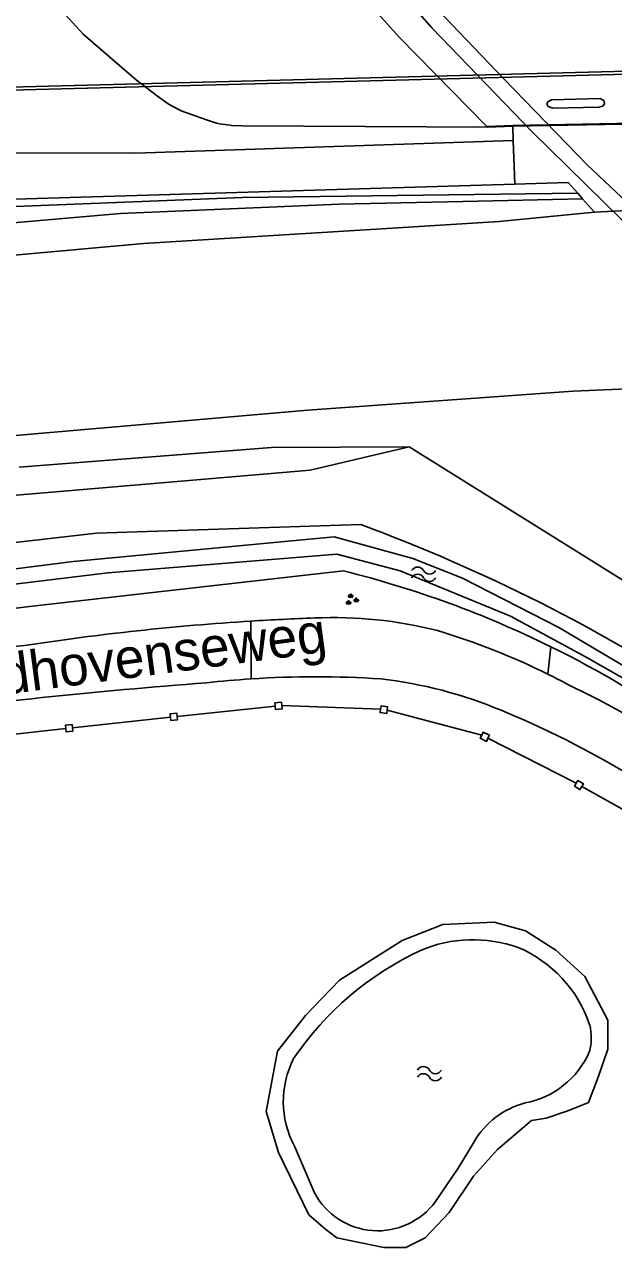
# Model space of a CAD drawing. Extents: x 135990 to 139000, y 393500 to 396000.
# Drawn here: x 137162.5 to 137199.5, y 395776.9 to 395853.7 of the extents above; entities that cross this region are included whole.
import ezdxf

# ---------------------------------------------------------------- set-up
doc = ezdxf.new("R2010")
doc.units = 0
for name, color, linetype in [('gg-afsc-hekwerk', 7, 'Continuous'), ('gg-afsc-muur', 7, 'Continuous'), ('gg-anno-openbare ruimte label', 7, 'Continuous'), ('gg-knt-BGT kruinlijn', 7, 'Continuous'), ('gg-knt-verharding', 7, 'Continuous'), ('gg-kntw-bovenkant insteek waterloop', 7, 'Continuous'), ('gg-kntw-waterlijn', 7, 'Continuous'), ('gg-kwrk-faunavoorziening', 7, 'Continuous'), ('gg-kwrk-kunstwerk niveau 01', 7, 'Continuous'), ('gt-grn-groengrens', 7, 'Continuous'), ('gt-grn-weggrens', 7, 'Continuous'), ('gt-symb-groenvak', 7, 'Continuous'), ('gt-symb-watersymbool', 7, 'Continuous'), ('gx-grn-maaiveld', 7, 'Continuous')]:
    doc.layers.add(name, color=color, linetype=linetype)

# ---------------------------------------------------------------- blocks, each defined once
blk = doc.blocks.new('gt0-GRVAK')
at = {"layer": 'gt-symb-groenvak'}
for p, q in [((-0.11, 0.189), (-0.228, 0.24)), ((-0.182, 0.153), (0.088, 0.153)), ((-0.091, 0.211), (-0.156, 0.322)), ((-0.047, 0.214), (-0.047, 0.393)), ((-0.004, 0.211), (0.061, 0.322)), ((0.015, 0.189), (0.133, 0.24)), ((0.262, -0.052), (0.197, 0.059)), ((0.305, -0.049), (0.305, 0.13)), ((0.349, -0.052), (0.414, 0.059)), ((-0.245, -0.228), (-0.363, -0.177)), ((-0.318, -0.264), (-0.047, -0.264)), ((-0.226, -0.206), (-0.291, -0.095)), ((-0.183, -0.203), (-0.183, -0.024)), ((-0.139, -0.206), (-0.074, -0.095)), ((-0.12, -0.228), (-0.002, -0.177)), ((0.243, -0.074), (0.125, -0.023)), ((0.17, -0.11), (0.441, -0.11)), ((0.368, -0.074), (0.486, -0.023))]:
    blk.add_line(p, q, dxfattribs=at)
blk = doc.blocks.new('gt0-WA')
at = {"layer": 'gt-symb-watersymbool'}
for centre, start, end in [((-0.323, 0.022), 28.07249, 151.92751), ((0.427, 0.422), 208.07248, 331.92751), ((-0.323, -0.428), 28.07249, 151.92751), ((0.427, -0.028), 208.07248, 331.92751)]:
    blk.add_arc(centre, 0.425, start, end, dxfattribs=at)

msp = doc.modelspace()

# ---------------------------------------------------------------- linework, layer by layer
at = {"layer": 'gg-afsc-hekwerk'}
for p, q in [((137178.271, 395810.926), (137172.107, 395810.279)), ((137178.271, 395810.926), (137172.107, 395810.279)), ((137178.689, 395810.968), (137184.876, 395810.739)), ((137178.689, 395810.968), (137184.876, 395810.739)), ((137185.29, 395810.681), (137186.617, 395810.327)), ((137185.29, 395810.681), (137186.617, 395810.327)), ((137171.689, 395810.241), (137165.544, 395809.566)), ((137171.689, 395810.241), (137165.544, 395809.566)), ((137186.617, 395810.327), (137191.218, 395809.1)), ((137186.617, 395810.327), (137191.218, 395809.1)), ((137165.125, 395809.535), (137158.966, 395808.841)), ((137165.125, 395809.535), (137158.966, 395808.841)), ((137191.615, 395808.91), (137197.144, 395806.089)), ((137191.615, 395808.91), (137197.144, 395806.089)), ((137197.495, 395805.877), (137202.906, 395802.862)), ((137197.495, 395805.877), (137202.906, 395802.862))]:
    msp.add_line(p, q, dxfattribs=at)
at = {"layer": 'gg-afsc-muur'}
for points in [[(137178.689, 395810.968), (137178.669, 395811.175), (137178.251, 395811.134), (137178.271, 395810.926)], [(137178.689, 395810.968), (137178.71, 395810.76), (137178.292, 395810.719), (137178.271, 395810.926)], [(137185.29, 395810.681), (137185.261, 395810.473), (137184.847, 395810.531), (137184.876, 395810.739)], [(137185.29, 395810.681), (137185.319, 395810.889), (137184.905, 395810.947), (137184.876, 395810.739)], [(137165.544, 395809.566), (137165.529, 395809.776), (137165.11, 395809.745), (137165.125, 395809.535)], [(137172.107, 395810.279), (137172.088, 395810.491), (137171.67, 395810.453), (137171.689, 395810.241)], [(137172.107, 395810.279), (137172.127, 395810.068), (137171.709, 395810.029), (137171.689, 395810.241)], [(137165.544, 395809.566), (137165.559, 395809.356), (137165.141, 395809.325), (137165.125, 395809.535)], [(137191.615, 395808.91), (137191.524, 395808.72), (137191.127, 395808.911), (137191.218, 395809.1)], [(137191.615, 395808.91), (137191.706, 395809.099), (137191.309, 395809.289), (137191.218, 395809.1)], [(137197.495, 395805.877), (137197.386, 395805.697), (137197.035, 395805.909), (137197.144, 395806.089)], [(137197.495, 395805.877), (137197.603, 395806.056), (137197.252, 395806.268), (137197.144, 395806.089)]]:
    msp.add_lwpolyline(points, dxfattribs=at)
at = {"layer": 'gg-knt-BGT kruinlijn'}
for p, q in [((137178.024, 395827.169), (137162.207, 395825.928)), ((137186.663, 395827.215), (137178.024, 395827.169))]:
    msp.add_line(p, q, dxfattribs=at)
msp.add_lwpolyline([(137092.226, 395833.606), (137099.988, 395834.818), (137105.894, 395835.651), (137111.463, 395836.46), (137116.876, 395837.408), (137122.429, 395838.307), (137129.831, 395839.156), (137136.568, 395839.864), (137142.557, 395840.521), (137146.722, 395840.897), (137149.415, 395840.991), (137151.889, 395840.889), (137157.241, 395840.874), (137163.262, 395841.406), (137168.559, 395841.856), (137175.926, 395842.169), (137182.267, 395842.447), (137190.034, 395842.604), (137197.551, 395842.78)], dxfattribs=at)
at = {"layer": 'gg-knt-verharding'}
msp.add_line((137192.786, 395810.523), (137192.444, 395810.669), dxfattribs=at)
for centre, radius, start, end in [((137186.403, 395660.502), 156.065, 93.54873, 98.79787), ((137186.55, 395657.859), 158.713, 92.09664, 93.54244), ((137181.905, 395789.863), 26.627, 75.76685, 92.50151), ((137175.427, 395772.596), 45.003, 63.68661, 73.17643), ((137196.095, 395406.981), 409.129, 94.70544, 99.73883), ((137174.749, 395771.265), 46.497, 61.99483, 63.6653), ((137201.614, 395448.868), 364.58, 94.35164, 97.60878), ((137180.792, 395750.403), 62.37, 93.71847, 96.29705), ((137180.808, 395750.713), 62.062, 86.23421, 93.7517), ((137181.77, 395785.227), 27.59, 67.24052, 83.5202), ((137162.487, 395742.046), 78.105, 57.45807, 64.11745), ((137169.53, 395755.208), 60.005, 64.88767, 67.19698), ((137169.235, 395754.525), 60.749, 56.21195, 64.90924)]:
    msp.add_arc(centre, radius, start, end, dxfattribs=at)
at = {"layer": 'gg-kntw-bovenkant insteek waterloop'}
for p, q in [((137167.056, 395821.795), (137183.632, 395822.326)), ((137162.838, 395817.179), (137182.557, 395819.42)), ((137180.725, 395780.382), (137179.469, 395783.311))]:
    msp.add_line(p, q, dxfattribs=at)
for points in [[(137000, 395789.345), (137007.08, 395791.511), (137047.79, 395801.851), (137091.42, 395811.382), (137130.73, 395817.622), (137167.056, 395821.795)], [(137162.838, 395817.179), (137131.48, 395813.262), (137090.45, 395806.152), (137047.99, 395796.692), (137042.383, 395795.217)], [(137180.383, 395778.992), (137178.462, 395782.915), (137177.692, 395785.49), (137178.409, 395789.266), (137180.156, 395791.518), (137182.292, 395793.722), (137186.226, 395796.225), (137188.774, 395797.223), (137191.993, 395797.364)], [(137180.383, 395778.992), (137181.446, 395778.081), (137182.129, 395777.549), (137185.088, 395776.942), (137186.454, 395776.942), (137187.668, 395777.549), (137189.185, 395779.144), (137190.703, 395781.421), (137192.221, 395783.091), (137194.345, 395784.913), (137195.256, 395785.065), (137196.622, 395785.521), (137197.912, 395786.052), (137198.519, 395787.646), (137199.126, 395789.393), (137199.126, 395791.215), (137197.684, 395793.948), (137195.863, 395795.618), (137193.966, 395796.832), (137191.993, 395797.364)], [(137188.322, 395779.831), (137189.748, 395781.932), (137190.742, 395783.578)]]:
    msp.add_lwpolyline(points, dxfattribs=at)
for centre, radius, start, end in [((137146.605, 395721.892), 107.042, 56.61581, 69.76268), ((137166.969, 395756.698), 64.63, 63.74429, 76.04345), ((137167.018, 395756.748), 64.563, 54.71856, 63.76314)]:
    msp.add_arc(centre, radius, start, end, dxfattribs=at)
at = {"layer": 'gg-kntw-waterlijn'}
for points in [[(136968.737, 395777.398), (136994.091, 395785.32), (137025.448, 395794.333), (137033.646, 395796.495), (137060.818, 395803.1), (137072.955, 395805.786), (137085.527, 395808.569), (137095.686, 395810.408), (137116.952, 395814.005), (137134.131, 395816.331), (137142.583, 395817.284), (137155.856, 395818.782), (137165.595, 395820.017), (137181.967, 395821.568), (137186.891, 395820.194), (137190.02, 395818.97), (137196.065, 395815.871), (137202.42, 395812.104)], [(137229.766, 395795.804), (137197.765, 395813.996), (137193.031, 395816.57), (137186.114, 395819.434), (137182.135, 395820.479), (137167.756, 395819.294), (137153.141, 395817.514), (137121.302, 395813.334), (137111.341, 395811.713), (137088.362, 395807.588), (137062.841, 395802.174), (137044.636, 395798.052), (137025.44, 395793.193), (137014.589, 395790.094), (136993.792, 395783.757), (136971.502, 395777.034)]]:
    msp.add_lwpolyline(points, dxfattribs=at)
for centre, radius, start, end in [((137190.683, 395787.81), 8.455, 70.5015, 112.99597), ((137195.809, 395777.638), 19.835, 115.14718, 145.72628), ((137190.394, 395788.399), 8.009, 18.42638, 67.14533), ((137194.865, 395790.117), 3.233, 344.06263, 14.59088), ((137192.922, 395791.437), 5.512, 280.74829, 336.39047), ((137184.742, 395786.109), 5.969, 153.11298, 207.95015), ((137195.294, 395780.929), 5.266, 104.78058, 149.80041), ((137184.696, 395782.487), 4.494, 207.92523, 323.77813)]:
    msp.add_arc(centre, radius, start, end, dxfattribs=at)
at = {"layer": 'gg-kwrk-faunavoorziening'}
msp.add_lwpolyline([(137160.001, 395849.554), (137159.996, 395849.754), (137235.826, 395851.724), (137235.831, 395851.524), (137160.001, 395849.554)], dxfattribs=at)
at = {"layer": 'gg-kwrk-kunstwerk niveau 01'}
for points in [[(137226.693, 395820.807), (137224.986, 395820.706), (137219.386, 395824.923), (137213.014, 395829.943), (137206.497, 395835.519), (137199.981, 395841.471), (137194.38, 395846.985), (137188.095, 395853.509), (137186.573, 395855.275), (137187.949, 395855.178)], [(137226.693, 395820.807), (137219.124, 395826.392), (137212.027, 395832.143), (137205.256, 395837.932), (137197.858, 395844.884), (137192.612, 395850.303), (137187.949, 395855.178)]]:
    msp.add_lwpolyline(points, dxfattribs=at)
at = {"layer": 'gt-grn-groengrens'}
msp.add_line((137195.56, 395814.66), (137195.376, 395812.936), dxfattribs=at)
at = {"layer": 'gt-grn-weggrens'}
msp.add_line((137176.743, 395816.268), (137176.747, 395812.642), dxfattribs=at)
at = {"layer": 'gx-grn-maaiveld'}
for p, q in [((137193.165, 395847.335), (137213.85, 395847.728)), ((137191.548, 395847.33), (137191.595, 395847.282)), ((137191.595, 395847.282), (137193.165, 395847.335)), ((137193.199, 395846.445), (137193.165, 395847.335)), ((137193.303, 395843.697), (137193.199, 395846.445)), ((137197.551, 395842.78), (137197.241, 395843.128)), ((137197.551, 395842.78), (137198.302, 395841.933)), ((137198.302, 395841.933), (137198.691, 395841.954)), ((137186.663, 395827.215), (137180.449, 395825.747)), ((137201.277, 395818.076), (137186.663, 395827.215)), ((137180.449, 395825.747), (137170.399, 395824.883)), ((137170.399, 395824.883), (137156.193, 395823.678))]:
    msp.add_line(p, q, dxfattribs=at)
for points in [[(137130.328, 395893.164), (137140.225, 395881.266), (137157.02, 395863.192), (137166.224, 395853.125), (137169.557, 395850.228), (137170.872, 395849.221), (137171.545, 395848.742), (137171.653, 395848.676), (137172.239, 395848.363), (137172.374, 395848.303), (137173.957, 395847.736), (137174.588, 395847.529), (137174.766, 395847.488), (137175.44, 395847.397), (137175.529, 395847.389), (137176.212, 395847.362), (137191.595, 395847.282)], [(137191.548, 395847.33), (137186.071, 395852.917), (137180.772, 395858.81)], [(137136.787, 395852.027), (137138.762, 395851.49), (137141.08, 395850.764), (137145.661, 395849.35), (137149.77, 395848.077), (137152.362, 395847.333), (137154.917, 395846.741), (137158.748, 395845.657), (137169.489, 395845.641), (137193.199, 395846.445)], [(137101.174, 395847.592), (137102.957, 395847.785), (137114.106, 395849.092), (137122.714, 395850.077), (137125.464, 395850.399), (137128.071, 395850.491), (137130.172, 395850.473), (137131.988, 395850.324), (137133.941, 395850.066), (137136.204, 395849.595), (137138.06, 395849.09), (137140.338, 395848.377), (137144.907, 395846.967), (137148.505, 395845.803), (137151.206, 395844.913), (137159.103, 395842.678), (137193.303, 395843.697)], [(137198.933, 395848.736), (137198.873, 395848.961), (137198.662, 395849.068), (137195.606, 395849.004), (137195.388, 395848.892), (137195.316, 395848.738), (137195.384, 395848.583), (137195.678, 395848.473), (137198.569, 395848.529), (137198.817, 395848.605), (137198.933, 395848.736)], [(137215.273, 395847.876), (137213.848, 395847.778), (137193.164, 395847.385), (137191.548, 395847.33)], [(137197.241, 395843.128), (137196.648, 395843.797), (137193.303, 395843.697)], [(137095.462, 395838.664), (137095.739, 395838.704), (137103.693, 395839.482), (137113.162, 395840.103), (137126.873, 395841.554), (137135.373, 395842.278), (137137.422, 395842.326), (137147.176, 395842.821), (137158.278, 395842.148), (137176.204, 395842.853), (137197.241, 395843.128)], [(137198.691, 395841.954), (137201.557, 395842.113), (137218.958, 395842.7), (137220.484, 395842.696)], [(137090.054, 395830.21), (137098.384, 395831.623), (137117.154, 395834.383), (137132.954, 395836.294), (137152.856, 395838.423), (137169.998, 395839.968), (137186.295, 395840.982), (137192.321, 395841.351), (137198.302, 395841.933)], [(137210.521, 395831.243), (137206.698, 395831.118), (137196.965, 395830.694), (137180.318, 395829.521), (137161, 395827.844), (137141.93, 395826.17), (137130.719, 395824.866)]]:
    msp.add_lwpolyline(points, dxfattribs=at)

# ---------------------------------------------------------------- block references
at = {"layer": 'gt-symb-groenvak'}
msp.add_blockref('gt0-GRVAK', (137183.049, 395817.612), dxfattribs=at)
at = {"layer": 'gt-symb-watersymbool'}
for p in [(137187.523, 395819.216), (137187.888, 395787.859)]:
    msp.add_blockref('gt0-WA', p, dxfattribs=at)

# ---------------------------------------------------------------- texts
at = {"layer": 'gg-anno-openbare ruimte label'}
msp.add_text('Eindhovenseweg', height=2.5, rotation=7.6, dxfattribs=at).set_placement((137156.37, 395810.988))

doc.saveas('drawing.dxf')
